// Mitsubishi GX Works2 project: FX3G_COM2_RS   PLC: FX3G

PROGRAM MAIN
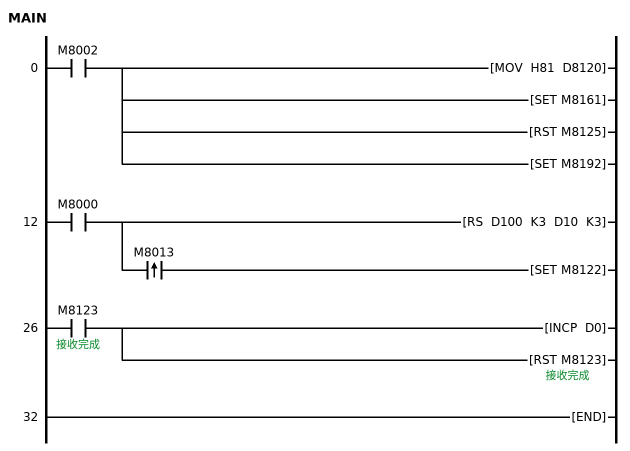
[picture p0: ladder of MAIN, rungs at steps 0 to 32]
0     LD      M8002
      MOV     H81 D8120
        [note] 通讯设定9600 8 N 1
      SET     M8161
        [note] on为8位模式，off：16位
      RST     M8125
      SET     M8192
12    LD      M8000
      RS      D100 K3 D10 K3
      ANDP    M8013
      SET     M8122
26    LD      M8123  ; 接收完成
      INCP    D0
        [note] 接收数量
      RST     M8123  ; 接收完成
32    END
END_PROGRAM

// device comments not shown above
D200  ; 写入数量，1个
D211  ; 转速
M2  ; 反转
M3  ; 停止
